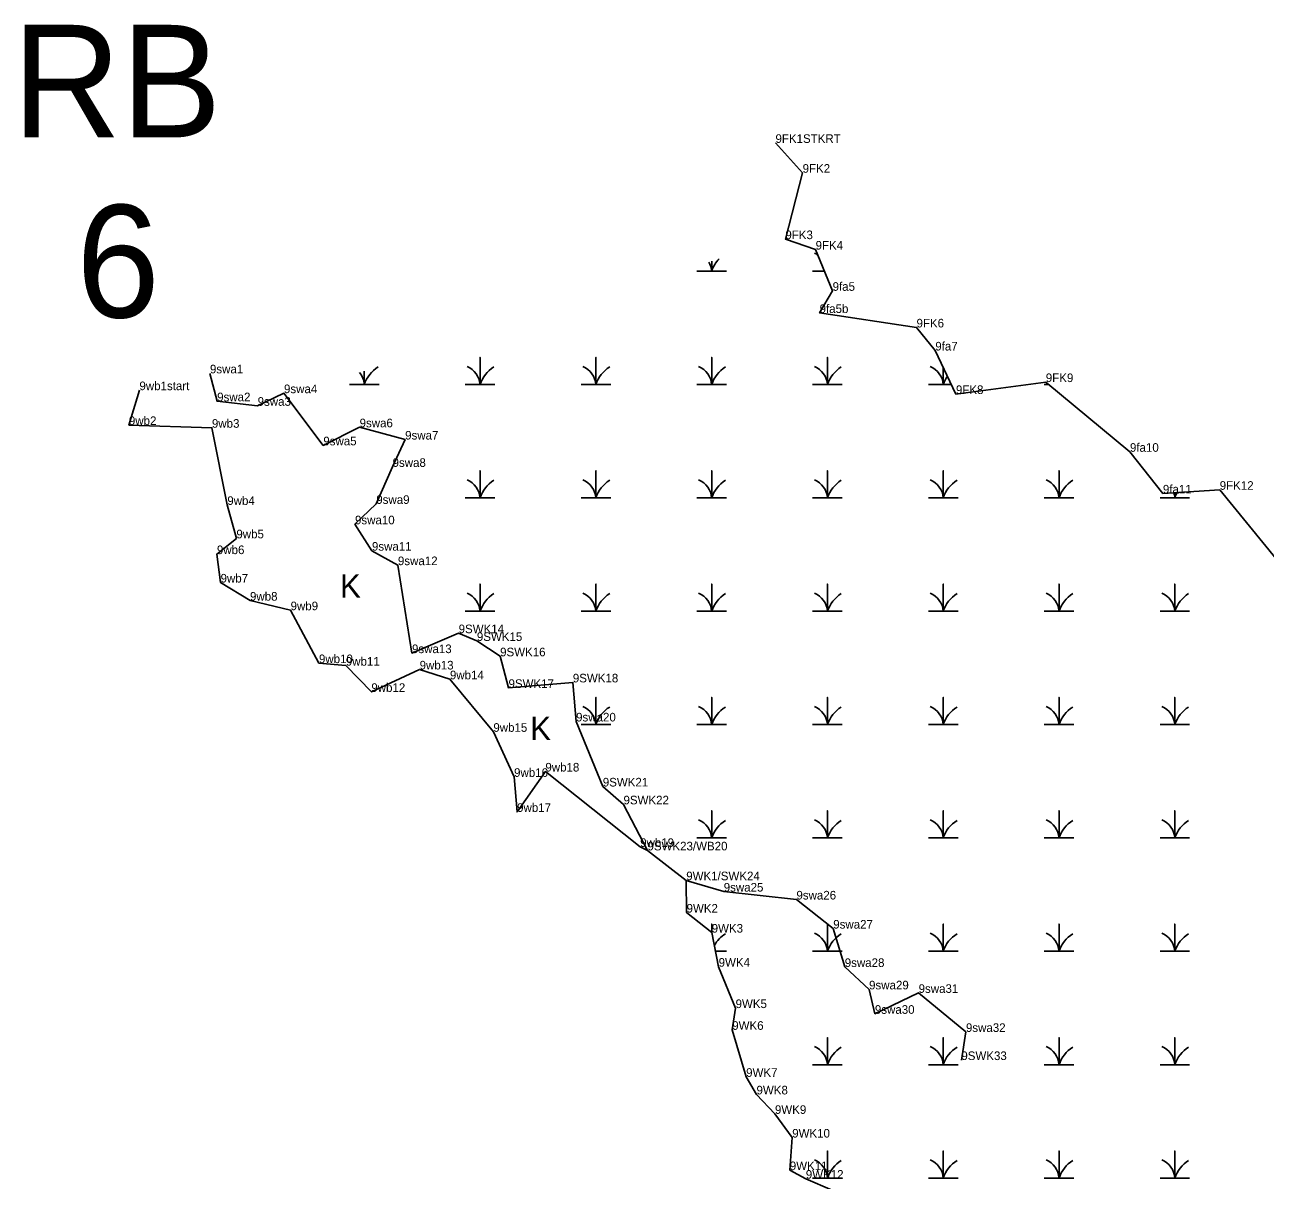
# Model space of a CAD drawing. Extents: x 2072529 to 2268796, y 436423 to 470397.
# Drawn here: x 2211830 to 2212551, y 449541 to 450212 of the extents above; entities that cross this region are included whole.
import ezdxf

# ---------------------------------------------------------------- set-up
doc = ezdxf.new("R2010")
doc.units = 0
for name, color, linetype in [('Default', 7, 'Continuous'), ('Exist Environmental Wetland Boundary', 7, 'Continuous'), ('Exist Environmental Wetland Boundary Cogo Comment', 7, 'Continuous'), ('Exist Environmental Wetland Boundary Cogo Point CELL', 7, 'Continuous'), ('Exist Hydro Jurisdictional Stream or Body of Water NEU Mitigable', 7, 'Continuous'), ('Exist Hydro Jurisdictional Stream or Body of Water NEU Mitigable Cogo Comment', 7, 'Continuous'), ('Exist Hydro Swamp or Marsh', 7, 'Continuous')]:
    doc.layers.add(name, color=color, linetype=linetype)

msp = doc.modelspace()

# ---------------------------------------------------------------- linework, layer by layer
at = {"layer": 'Exist Environmental Wetland Boundary'}
for points in [[(2212266.45, 450143.23), (2212282.21, 450125.91), (2212272.2, 450087.37), (2212289.74, 450081.3), (2212299.63, 450057.38), (2212292.08, 450044.5), (2212348.37, 450036.11), (2212359.27, 450022.73), (2212371.25, 449997.47), (2212423.46, 450004.4), (2212472.32, 449963.94), (2212491.46, 449939.73), (2212524.45, 449941.86), (2212557.2, 449901.85)], [(2212192.12, 449732.56), (2212187.87, 449734.56), (2212132.83, 449778.34), (2212116.4, 449754.91), (2212114.63, 449775.24), (2212102.59, 449801.39), (2212077.37, 449831.86), (2212059.78, 449837.58), (2212031.73, 449824.56), (2212016.91, 449839.79), (2212001.31, 449841.26), (2211984.83, 449871.96), (2211961.26, 449877.54), (2211944.17, 449888.04), (2211942.04, 449904.54), (2211953.34, 449913.7), (2211948.07, 449933.08), (2211939.14, 449977.89), (2211890.93, 449979.47), (2211897.05, 449999.7)], [(2212299.43, 449535.26), (2212284.07, 449542), (2212274.77, 449546.95), (2212276.16, 449565.86), (2212266.13, 449579.6), (2212255.44, 449590.92), (2212249.41, 449601.12), (2212241.33, 449628.41), (2212243.27, 449641.04), (2212233.43, 449665.04), (2212229.4, 449684.82), (2212214.82, 449696.44), (2212214.5, 449715.1)]]:
    msp.add_lwpolyline(points, dxfattribs=at)
at = {"layer": 'Exist Environmental Wetland Boundary Cogo Point CELL'}
for p, q in [((2212266.45, 450143.23), (2212266.45, 450143.23)), ((2212282.21, 450125.91), (2212282.21, 450125.91)), ((2212272.2, 450087.37), (2212272.2, 450087.37)), ((2212289.74, 450081.3), (2212289.74, 450081.3)), ((2212299.63, 450057.38), (2212299.63, 450057.38)), ((2212299.63, 450057.38), (2212299.63, 450057.38)), ((2212292.08, 450044.5), (2212292.08, 450044.5)), ((2212292.08, 450044.5), (2212292.08, 450044.5)), ((2212348.37, 450036.11), (2212348.37, 450036.11)), ((2212359.27, 450022.73), (2212359.27, 450022.73)), ((2212359.27, 450022.73), (2212359.27, 450022.73)), ((2211938, 450009.47), (2211938, 450009.47)), ((2211897.05, 449999.7), (2211897.05, 449999.7)), ((2211981, 449997.97), (2211981, 449997.97)), ((2212423.46, 450004.4), (2212423.46, 450004.4)), ((2211942.18, 449993.25), (2211942.18, 449993.25)), ((2211965.69, 449990.64), (2211965.69, 449990.64)), ((2212371.25, 449997.47), (2212371.25, 449997.47)), ((2211890.93, 449979.47), (2211890.93, 449979.47)), ((2211939.14, 449977.89), (2211939.14, 449977.89)), ((2212024.9, 449978.15), (2212024.9, 449978.15)), ((2212051.36, 449971.04), (2212051.36, 449971.04)), ((2212003.85, 449967.68), (2212003.85, 449967.68)), ((2212472.32, 449963.94), (2212472.32, 449963.94)), ((2212472.32, 449963.94), (2212472.32, 449963.94)), ((2212044.07, 449955.16), (2212044.07, 449955.16)), ((2212524.45, 449941.86), (2212524.45, 449941.86)), ((2211948.07, 449933.08), (2211948.07, 449933.08)), ((2212034.6, 449933.69), (2212034.6, 449933.69)), ((2212491.46, 449939.73), (2212491.46, 449939.73)), ((2212491.46, 449939.73), (2212491.46, 449939.73)), ((2212022.23, 449921.84), (2212022.23, 449921.84)), ((2211953.34, 449913.7), (2211953.34, 449913.7)), ((2211942.04, 449904.54), (2211942.04, 449904.54)), ((2212032.07, 449906.53), (2212032.07, 449906.53)), ((2212047.16, 449898.13), (2212047.16, 449898.13)), ((2211944.17, 449888.04), (2211944.17, 449888.04)), ((2211961.26, 449877.54), (2211961.26, 449877.54)), ((2211984.83, 449871.96), (2211984.83, 449871.96)), ((2212082.43, 449858.63), (2212082.43, 449858.63)), ((2212093.02, 449854.12), (2212093.02, 449854.12)), ((2212055.34, 449847.07), (2212055.34, 449847.07)), ((2212001.31, 449841.26), (2212001.31, 449841.26)), ((2212016.91, 449839.79), (2212016.91, 449839.79)), ((2212106.52, 449845.21), (2212106.52, 449845.21)), ((2212059.78, 449837.58), (2212059.78, 449837.58)), ((2212077.37, 449831.86), (2212077.37, 449831.86)), ((2212111.4, 449826.87), (2212111.4, 449826.87)), ((2212148.76, 449830.07), (2212148.76, 449830.07)), ((2212031.73, 449824.56), (2212031.73, 449824.56)), ((2212150.66, 449807.4), (2212150.66, 449807.4)), ((2212102.59, 449801.39), (2212102.59, 449801.39)), ((2212114.63, 449775.24), (2212114.63, 449775.24)), ((2212132.83, 449778.34), (2212132.83, 449778.34)), ((2212166.16, 449769.66), (2212166.16, 449769.66)), ((2212116.4, 449754.91), (2212116.4, 449754.91)), ((2212178.19, 449759.28), (2212178.19, 449759.28)), ((2212187.85, 449734.53), (2212187.85, 449734.53)), ((2212192.12, 449732.56), (2212192.12, 449732.56)), ((2212192.12, 449732.56), (2212192.12, 449732.56)), ((2212214.5, 449715.1), (2212214.5, 449715.1)), ((2212214.5, 449715.1), (2212214.5, 449715.1)), ((2212236.4, 449708.65), (2212236.4, 449708.65)), ((2212278.62, 449704.05), (2212278.62, 449704.05)), ((2212214.82, 449696.44), (2212214.82, 449696.44)), ((2212229.4, 449684.82), (2212229.4, 449684.82)), ((2212299.99, 449687.16), (2212299.99, 449687.16)), ((2212233.43, 449665.04), (2212233.43, 449665.04)), ((2212306.69, 449664.9), (2212306.69, 449664.9)), ((2212320.81, 449651.88), (2212320.81, 449651.88)), ((2212349.58, 449649.84), (2212349.58, 449649.84)), ((2212243.27, 449641.04), (2212243.27, 449641.04)), ((2212324.18, 449637.71), (2212324.18, 449637.71)), ((2212241.33, 449628.41), (2212241.33, 449628.41)), ((2212377.06, 449627.18), (2212377.06, 449627.18)), ((2212374.41, 449610.86), (2212374.41, 449610.86)), ((2212249.41, 449601.12), (2212249.41, 449601.12)), ((2212255.44, 449590.92), (2212255.44, 449590.92)), ((2212266.13, 449579.6), (2212266.13, 449579.6)), ((2212276.16, 449565.86), (2212276.16, 449565.86)), ((2212274.77, 449546.95), (2212274.77, 449546.95)), ((2212284.07, 449542), (2212284.07, 449542))]:
    msp.add_line(p, q, dxfattribs=at)
at = {"layer": 'Exist Hydro Jurisdictional Stream or Body of Water NEU Mitigable'}
msp.add_lwpolyline([(2211938, 450009.47), (2211942.18, 449993.25), (2211965.69, 449990.64), (2211981, 449997.97), (2212003.85, 449967.68), (2212024.9, 449978.15), (2212051.36, 449971.04), (2212044.07, 449955.16), (2212034.6, 449933.69), (2212022.23, 449921.84), (2212032.07, 449906.53), (2212047.16, 449898.13), (2212055.34, 449847.07), (2212082.43, 449858.63), (2212093.02, 449854.12), (2212106.52, 449845.21), (2212111.4, 449826.87), (2212148.76, 449830.07), (2212150.66, 449807.4), (2212166.16, 449769.66), (2212178.19, 449759.28), (2212192.12, 449732.56), (2212214.5, 449715.1), (2212236.4, 449708.65), (2212278.62, 449704.05), (2212299.99, 449687.16), (2212306.69, 449664.9), (2212320.81, 449651.88), (2212324.18, 449637.71), (2212349.58, 449649.84), (2212377.06, 449627.18), (2212374.41, 449610.86)], dxfattribs=at)
at = {"layer": 'Exist Hydro Swamp or Marsh'}
for points in [[(2212220.78, 450068.77), (2212229.39, 450068.77), (2212229.39, 450074.57)], [(2212229.39, 450074.57), (2212229.39, 450068.77), (2212237.99, 450068.77)], [(2212288.03, 450068.77), (2212294.92, 450068.77)], [(2212086.28, 450002.97), (2212094.89, 450002.97), (2212094.89, 450018.75), (2212094.89, 450002.97), (2212103.49, 450002.97)], [(2212153.53, 450002.97), (2212162.14, 450002.97), (2212162.14, 450018.75), (2212162.14, 450002.97), (2212170.74, 450002.97)], [(2212220.78, 450002.97), (2212229.39, 450002.97), (2212229.39, 450018.75), (2212229.39, 450002.97), (2212237.99, 450002.97)], [(2212288.03, 450002.97), (2212296.64, 450002.97), (2212296.64, 450018.75), (2212296.64, 450002.97), (2212305.24, 450002.97)], [(2212355.28, 450002.97), (2212363.89, 450002.97), (2212363.89, 450013)], [(2212363.89, 450013), (2212363.89, 450002.97), (2212368.64, 450002.97)], [(2212019.03, 450002.97), (2212027.64, 450002.97), (2212027.64, 450010.77)], [(2212027.64, 450010.77), (2212027.64, 450002.97), (2212036.24, 450002.97)], [(2212422.53, 450002.97), (2212425.18, 450002.97)], [(2212086.28, 449937.17), (2212094.89, 449937.17), (2212094.89, 449952.95), (2212094.89, 449937.17), (2212103.49, 449937.17)], [(2212153.53, 449937.17), (2212162.14, 449937.17), (2212162.14, 449952.95), (2212162.14, 449937.17), (2212170.74, 449937.17)], [(2212220.78, 449937.17), (2212229.39, 449937.17), (2212229.39, 449952.95), (2212229.39, 449937.17), (2212237.99, 449937.17)], [(2212288.03, 449937.17), (2212296.64, 449937.17), (2212296.64, 449952.95), (2212296.64, 449937.17), (2212305.24, 449937.17)], [(2212355.28, 449937.17), (2212363.89, 449937.17), (2212363.89, 449952.95), (2212363.89, 449937.17), (2212372.49, 449937.17)], [(2212422.53, 449937.17), (2212431.14, 449937.17), (2212431.14, 449952.95), (2212431.14, 449937.17), (2212439.74, 449937.17)], [(2212489.78, 449937.17), (2212498.39, 449937.17), (2212498.39, 449940.18)], [(2212498.39, 449940.18), (2212498.39, 449937.17), (2212506.99, 449937.17)], [(2212036.13, 449937.17), (2212036.24, 449937.17)], [(2212086.28, 449871.37), (2212094.89, 449871.37), (2212094.89, 449887.15), (2212094.89, 449871.37), (2212103.49, 449871.37)], [(2212153.53, 449871.37), (2212162.14, 449871.37), (2212162.14, 449887.15), (2212162.14, 449871.37), (2212170.74, 449871.37)], [(2212220.78, 449871.37), (2212229.39, 449871.37), (2212229.39, 449887.15), (2212229.39, 449871.37), (2212237.99, 449871.37)], [(2212288.03, 449871.37), (2212296.64, 449871.37), (2212296.64, 449887.15), (2212296.64, 449871.37), (2212305.24, 449871.37)], [(2212355.28, 449871.37), (2212363.89, 449871.37), (2212363.89, 449887.15), (2212363.89, 449871.37), (2212372.49, 449871.37)], [(2212422.53, 449871.37), (2212431.14, 449871.37), (2212431.14, 449887.15), (2212431.14, 449871.37), (2212439.74, 449871.37)], [(2212489.78, 449871.37), (2212498.39, 449871.37), (2212498.39, 449887.15), (2212498.39, 449871.37), (2212506.99, 449871.37)], [(2212153.53, 449805.57), (2212162.14, 449805.57), (2212162.14, 449821.35), (2212162.14, 449805.57), (2212170.74, 449805.57)], [(2212220.78, 449805.57), (2212229.39, 449805.57), (2212229.39, 449821.35), (2212229.39, 449805.57), (2212237.99, 449805.57)], [(2212288.03, 449805.57), (2212296.64, 449805.57), (2212296.64, 449821.35), (2212296.64, 449805.57), (2212305.24, 449805.57)], [(2212355.28, 449805.57), (2212363.89, 449805.57), (2212363.89, 449821.35), (2212363.89, 449805.57), (2212372.49, 449805.57)], [(2212422.53, 449805.57), (2212431.14, 449805.57), (2212431.14, 449821.35), (2212431.14, 449805.57), (2212439.74, 449805.57)], [(2212489.78, 449805.57), (2212498.39, 449805.57), (2212498.39, 449821.35), (2212498.39, 449805.57), (2212506.99, 449805.57)], [(2212220.78, 449739.77), (2212229.39, 449739.77), (2212229.39, 449755.55), (2212229.39, 449739.77), (2212237.99, 449739.77)], [(2212288.03, 449739.77), (2212296.64, 449739.77), (2212296.64, 449755.55), (2212296.64, 449739.77), (2212305.24, 449739.77)], [(2212355.28, 449739.77), (2212363.89, 449739.77), (2212363.89, 449755.55), (2212363.89, 449739.77), (2212372.49, 449739.77)], [(2212422.53, 449739.77), (2212431.14, 449739.77), (2212431.14, 449755.55), (2212431.14, 449739.77), (2212439.74, 449739.77)], [(2212489.78, 449739.77), (2212498.39, 449739.77), (2212498.39, 449755.55), (2212498.39, 449739.77), (2212506.99, 449739.77)], [(2212229.39, 449684.83), (2212229.39, 449689.75), (2212229.39, 449684.83)], [(2212288.03, 449673.97), (2212296.64, 449673.97), (2212296.64, 449689.75), (2212296.64, 449673.97), (2212305.24, 449673.97)], [(2212355.28, 449673.97), (2212363.89, 449673.97), (2212363.89, 449689.75), (2212363.89, 449673.97), (2212372.49, 449673.97)], [(2212422.53, 449673.97), (2212431.14, 449673.97), (2212431.14, 449689.75), (2212431.14, 449673.97), (2212439.74, 449673.97)], [(2212489.78, 449673.97), (2212498.39, 449673.97), (2212498.39, 449689.75), (2212498.39, 449673.97), (2212506.99, 449673.97)], [(2212231.61, 449673.97), (2212237.99, 449673.97)], [(2212288.03, 449608.17), (2212296.64, 449608.17), (2212296.64, 449623.95), (2212296.64, 449608.17), (2212305.24, 449608.17)], [(2212355.28, 449608.17), (2212363.89, 449608.17), (2212363.89, 449623.95), (2212363.89, 449608.17), (2212372.49, 449608.17)], [(2212422.53, 449608.17), (2212431.14, 449608.17), (2212431.14, 449623.95), (2212431.14, 449608.17), (2212439.74, 449608.17)], [(2212489.78, 449608.17), (2212498.39, 449608.17), (2212498.39, 449623.95), (2212498.39, 449608.17), (2212506.99, 449608.17)], [(2212288.03, 449542.37), (2212296.64, 449542.37), (2212296.64, 449558.15), (2212296.64, 449542.37), (2212305.24, 449542.37)], [(2212355.28, 449542.37), (2212363.89, 449542.37), (2212363.89, 449558.15), (2212363.89, 449542.37), (2212372.49, 449542.37)], [(2212422.53, 449542.37), (2212431.14, 449542.37), (2212431.14, 449558.15), (2212431.14, 449542.37), (2212439.74, 449542.37)], [(2212489.78, 449542.37), (2212498.39, 449542.37), (2212498.39, 449558.15), (2212498.39, 449542.37), (2212506.99, 449542.37)]]:
    msp.add_lwpolyline(points, dxfattribs=at)
for centre, radius, start, end in [((2212284.37, 450067.88), 12.3, 57.34248, 67.53497), ((2212217.12, 450067.88), 12.3, 4.14034, 30.12475), ((2212247.63, 450062.71), 19.22, 136.57429, 161.62219), ((2212045.88, 449996.91), 19.22, 122.12745, 161.62219), ((2212082.62, 450002.08), 12.3, 4.14034, 67.53497), ((2212113.13, 449996.91), 19.22, 122.12745, 161.62219), ((2212149.87, 450002.08), 12.3, 4.14034, 67.53497), ((2212180.38, 449996.91), 19.22, 122.12745, 161.62219), ((2212217.12, 450002.08), 12.3, 4.14034, 67.53497), ((2212247.63, 449996.91), 19.22, 122.12745, 161.62219), ((2212284.37, 450002.08), 12.3, 4.14034, 67.53497), ((2212314.88, 449996.91), 19.22, 122.12745, 161.62219), ((2212351.62, 450002.08), 12.3, 4.14034, 67.53497), ((2212015.37, 450002.08), 12.3, 4.14034, 39.4646), ((2212382.13, 449996.91), 19.22, 145.28894, 161.62219), ((2212082.62, 449936.28), 12.3, 4.14034, 67.53497), ((2212113.13, 449931.11), 19.22, 122.12745, 161.62219), ((2212149.87, 449936.28), 12.3, 4.14034, 67.53497), ((2212180.38, 449931.11), 19.22, 122.12745, 161.62219), ((2212217.12, 449936.28), 12.3, 4.14034, 67.53497), ((2212247.63, 449931.11), 19.22, 122.12745, 161.62219), ((2212284.37, 449936.28), 12.3, 4.14034, 67.53497), ((2212314.88, 449931.11), 19.22, 122.12745, 161.62219), ((2212351.62, 449936.28), 12.3, 4.14034, 67.53497), ((2212382.13, 449931.11), 19.22, 122.12745, 161.62219), ((2212418.87, 449936.28), 12.3, 4.14034, 67.53497), ((2212449.38, 449931.11), 19.22, 122.12745, 161.62219), ((2212486.12, 449936.28), 12.3, 4.14034, 18.30304), ((2212516.63, 449931.11), 19.22, 151.54291, 161.62219), ((2212082.62, 449870.48), 12.3, 4.14034, 67.53497), ((2212113.13, 449865.31), 19.22, 122.12745, 161.62219), ((2212149.87, 449870.48), 12.3, 4.14034, 67.53497), ((2212180.38, 449865.31), 19.22, 122.12745, 161.62219), ((2212217.12, 449870.48), 12.3, 4.14034, 67.53497), ((2212247.63, 449865.31), 19.22, 122.12745, 161.62219), ((2212284.37, 449870.48), 12.3, 4.14034, 67.53497), ((2212314.88, 449865.31), 19.22, 122.12745, 161.62219), ((2212351.62, 449870.48), 12.3, 4.14034, 67.53497), ((2212382.13, 449865.31), 19.22, 122.12745, 161.62219), ((2212418.87, 449870.48), 12.3, 4.14034, 67.53497), ((2212449.38, 449865.31), 19.22, 122.12745, 161.62219), ((2212486.12, 449870.48), 12.3, 4.14034, 67.53497), ((2212516.63, 449865.31), 19.22, 122.12745, 161.62219), ((2212149.87, 449804.68), 12.3, 4.14034, 67.53497), ((2212180.38, 449799.51), 19.22, 122.12745, 161.62219), ((2212217.12, 449804.68), 12.3, 4.14034, 67.53497), ((2212247.63, 449799.51), 19.22, 122.12745, 161.62219), ((2212284.37, 449804.68), 12.3, 4.14034, 67.53497), ((2212314.88, 449799.51), 19.22, 122.12745, 161.62219), ((2212351.62, 449804.68), 12.3, 4.14034, 67.53497), ((2212382.13, 449799.51), 19.22, 122.12745, 161.62219), ((2212418.87, 449804.68), 12.3, 4.14034, 67.53497), ((2212449.38, 449799.51), 19.22, 122.12745, 161.62219), ((2212486.12, 449804.68), 12.3, 4.14034, 67.53497), ((2212516.63, 449799.51), 19.22, 122.12745, 161.62219), ((2212217.12, 449738.88), 12.3, 4.14034, 67.53497), ((2212247.63, 449733.71), 19.22, 122.12745, 161.62219), ((2212284.37, 449738.88), 12.3, 4.14034, 67.53497), ((2212314.88, 449733.71), 19.22, 122.12745, 161.62219), ((2212351.62, 449738.88), 12.3, 4.14034, 67.53497), ((2212382.13, 449733.71), 19.22, 122.12745, 161.62219), ((2212418.87, 449738.88), 12.3, 4.14034, 67.53497), ((2212449.38, 449733.71), 19.22, 122.12745, 161.62219), ((2212486.12, 449738.88), 12.3, 4.14034, 67.53497), ((2212516.63, 449733.71), 19.22, 122.12745, 161.62219), ((2212247.63, 449667.91), 19.22, 122.12745, 150.42062), ((2212284.37, 449673.08), 12.3, 4.14034, 67.53497), ((2212314.88, 449667.91), 19.22, 122.12745, 161.62219), ((2212351.62, 449673.08), 12.3, 4.14034, 67.53497), ((2212382.13, 449667.91), 19.22, 122.12745, 161.62219), ((2212418.87, 449673.08), 12.3, 4.14034, 67.53497), ((2212449.38, 449667.91), 19.22, 122.12745, 161.62219), ((2212486.12, 449673.08), 12.3, 4.14034, 67.53497), ((2212516.63, 449667.91), 19.22, 122.12745, 161.62219), ((2212284.37, 449607.28), 12.3, 4.14034, 67.53497), ((2212314.88, 449602.11), 19.22, 122.12745, 161.62219), ((2212351.62, 449607.28), 12.3, 4.14034, 67.53497), ((2212382.13, 449602.11), 19.22, 122.12745, 161.62219), ((2212418.87, 449607.28), 12.3, 4.14034, 67.53497), ((2212449.38, 449602.11), 19.22, 122.12745, 161.62219), ((2212486.12, 449607.28), 12.3, 4.14034, 67.53497), ((2212516.63, 449602.11), 19.22, 122.12745, 161.62219), ((2212284.37, 449541.48), 12.3, 4.14034, 67.53497), ((2212314.88, 449536.31), 19.22, 122.12745, 161.62219), ((2212351.62, 449541.48), 12.3, 4.14034, 67.53497), ((2212382.13, 449536.31), 19.22, 122.12745, 161.62219), ((2212418.87, 449541.48), 12.3, 4.14034, 67.53497), ((2212449.38, 449536.31), 19.22, 122.12745, 161.62219), ((2212486.12, 449541.48), 12.3, 4.14034, 67.53497), ((2212516.63, 449536.31), 19.22, 122.12745, 161.62219)]:
    msp.add_arc(centre, radius, start, end, dxfattribs=at)

# ---------------------------------------------------------------- texts
at = {"layer": 'Default'}
for s, p in [('RB', (2211823.3, 450146.43)), ('6', (2211860.32, 450041.89))]:
    msp.add_text(s, height=65.34, dxfattribs=at).set_placement(p)
at = {"layer": 'Exist Environmental Wetland Boundary Cogo Comment'}
for s, p in [('9FK1STKRT', (2212266.45, 450143.23)), ('9FK2', (2212282.21, 450125.91)), ('9FK3', (2212272.2, 450087.37)), ('9FK4', (2212289.74, 450081.3)), ('9fa5', (2212299.63, 450057.38)), ('9fa5b', (2212292.08, 450044.5)), ('9FK6', (2212348.37, 450036.11)), ('9fa7', (2212359.27, 450022.73)), ('9wb1start', (2211897.05, 449999.7)), ('9FK9', (2212423.46, 450004.4)), ('9FK8', (2212371.25, 449997.47)), ('9wb2', (2211890.93, 449979.47)), ('9wb3', (2211939.14, 449977.89)), ('9fa10', (2212472.32, 449963.94)), ('9fa11', (2212491.46, 449939.73)), ('9FK12', (2212524.45, 449941.86)), ('9wb4', (2211948.07, 449933.08)), ('9wb5', (2211953.34, 449913.7)), ('9wb6', (2211942.04, 449904.54)), ('9wb7', (2211944.17, 449888.04)), ('9wb8', (2211961.26, 449877.54)), ('9wb9', (2211984.83, 449871.96)), ('9wb10', (2212001.31, 449841.26)), ('9wb11', (2212016.91, 449839.79)), ('9wb13', (2212059.78, 449837.58)), ('9wb14', (2212077.37, 449831.86)), ('9wb12', (2212031.73, 449824.56)), ('9wb15', (2212102.59, 449801.39)), ('9wb18', (2212132.83, 449778.34)), ('9wb16', (2212114.63, 449775.24)), ('9wb17', (2212116.4, 449754.91)), ('9WK2', (2212214.82, 449696.44)), ('9WK3', (2212229.4, 449684.82)), ('9WK4', (2212233.43, 449665.04)), ('9WK5', (2212243.27, 449641.04)), ('9WK6', (2212241.33, 449628.41)), ('9WK7', (2212249.41, 449601.12)), ('9WK8', (2212255.44, 449590.92)), ('9WK9', (2212266.13, 449579.6)), ('9WK10', (2212276.16, 449565.86)), ('9WK11', (2212274.77, 449546.95)), ('9WK12', (2212284.07, 449542))]:
    msp.add_text(s, height=5, dxfattribs=at).set_placement(p)
at = {"layer": 'Exist Hydro Jurisdictional Stream or Body of Water NEU Mitigable Cogo Comment'}
for s, p in [('9swa1', (2211938, 450009.47)), ('9swa2', (2211942.18, 449993.25)), ('9swa4', (2211981, 449997.97)), ('9swa3', (2211965.69, 449990.64)), ('9swa6', (2212024.9, 449978.15)), ('9swa7', (2212051.36, 449971.04)), ('9swa5', (2212003.85, 449967.68)), ('9swa8', (2212044.07, 449955.16)), ('9swa9', (2212034.6, 449933.69)), ('9swa10', (2212022.23, 449921.84)), ('9swa11', (2212032.07, 449906.53)), ('9swa12', (2212047.16, 449898.13)), ('9SWK14', (2212082.43, 449858.63)), ('9SWK15', (2212093.02, 449854.12)), ('9swa13', (2212055.34, 449847.07)), ('9SWK16', (2212106.52, 449845.21)), ('9SWK17', (2212111.4, 449826.87)), ('9SWK18', (2212148.76, 449830.07)), ('9swa20', (2212150.66, 449807.4)), ('9SWK21', (2212166.16, 449769.66)), ('9SWK22', (2212178.19, 449759.28)), ('9wb19', (2212187.87, 449734.56)), ('9SWK23/WB20', (2212192.12, 449732.56)), ('9WK1/SWK24', (2212214.62, 449715.21)), ('9swa25', (2212236.4, 449708.65)), ('9swa26', (2212278.62, 449704.05)), ('9swa27', (2212299.99, 449687.16)), ('9swa28', (2212306.69, 449664.9)), ('9swa29', (2212320.81, 449651.88)), ('9swa31', (2212349.58, 449649.84)), ('9swa30', (2212324.18, 449637.71)), ('9swa32', (2212377.06, 449627.18)), ('9SWK33', (2212374.41, 449610.86))]:
    msp.add_text(s, height=5, dxfattribs=at).set_placement(p)
at = {"layer": 'Exist Hydro Swamp or Marsh'}
for p in [(2212013.5, 449879.28), (2212123.98, 449796.55)]:
    msp.add_text('K', height=13.6, dxfattribs=at).set_placement(p)

doc.saveas('drawing.dxf')
